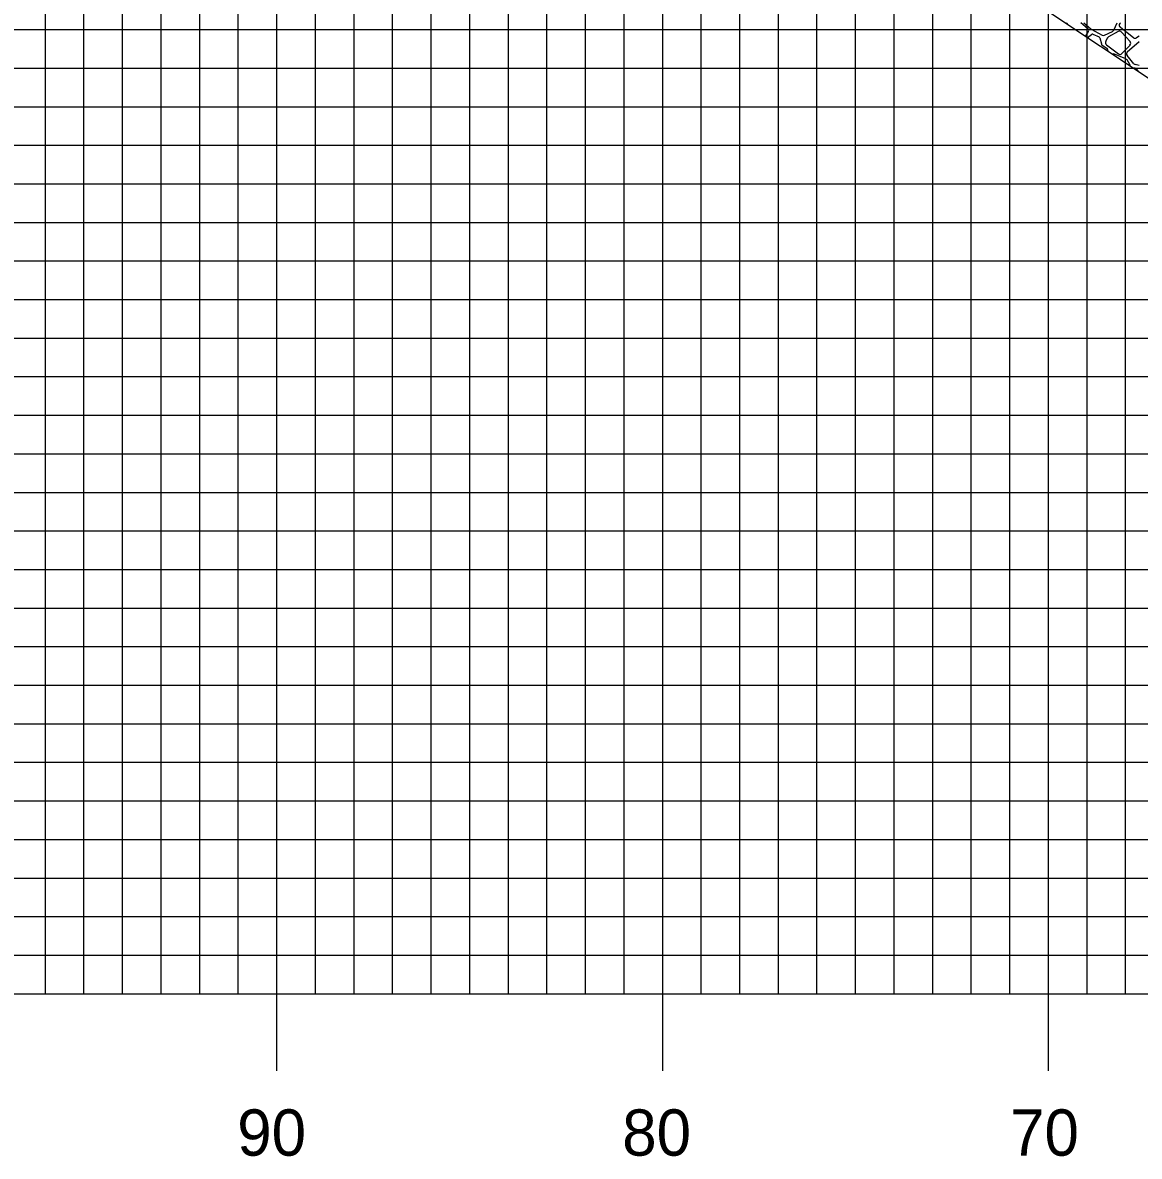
# Model space of a CAD drawing. Extents: x 1770055 to 1770398, y 442591 to 442811.
# Drawn here: x 1770123.94 to 1770152.88, y 442679.45 to 442708.84 of the extents above; entities that cross this region are included whole.
import ezdxf

# ---------------------------------------------------------------- set-up
doc = ezdxf.new("R2010")
doc.units = 0
for name, color, linetype in [('ANNOTATION', 7, 'Continuous'), ('GRUBBING IN FILL', 7, 'Continuous'), ('H_V ANNOTATION', 7, 'Continuous'), ('MAJOR', 7, 'Continuous'), ('MINOR', 7, 'Continuous')]:
    doc.layers.add(name, color=color, linetype=linetype)

msp = doc.modelspace()

# ---------------------------------------------------------------- linework, layer by layer
at = {"layer": 'ANNOTATION'}
msp.add_lwpolyline([(1770184.461, 442686.509), (1770130.169, 442722.703), (1770129.162, 442723.293), (1770128.291, 442723.662), (1770127.48, 442723.874), (1770126.762, 442723.946)], dxfattribs=at)
at = {"layer": 'GRUBBING IN FILL'}
for p, q in [((1770151.015, 442708.844), (1770150.997, 442708.817)), ((1770151.548, 442708.687), (1770151.367, 442708.844)), ((1770151.444, 442708.844), (1770151.625, 442708.682)), ((1770152.221, 442708.652), (1770152.304, 442708.844)), ((1770152.374, 442708.821), (1770152.392, 442708.844)), ((1770151.496, 442708.503), (1770151.559, 442708.597)), ((1770151.536, 442708.459), (1770151.645, 442708.541)), ((1770151.638, 442708.673), (1770151.917, 442708.52)), ((1770151.679, 442708.544), (1770151.842, 442708.473)), ((1770151.979, 442708.518), (1770152.188, 442708.618)), ((1770152.337, 442708.616), (1770152.083, 442708.476)), ((1770152.445, 442708.677), (1770152.385, 442708.725)), ((1770152.642, 442708.354), (1770152.421, 442708.601)), ((1770152.565, 442708.58), (1770152.446, 442708.677)), ((1770152.733, 442708.455), (1770152.567, 442708.578)), ((1770151.861, 442708.449), (1770151.899, 442708.293)), ((1770151.912, 442708.273), (1770152.047, 442708.174)), ((1770152.055, 442708.447), (1770152.01, 442708.358)), ((1770152.03, 442708.273), (1770152.341, 442708.035)), ((1770152.432, 442708.042), (1770152.641, 442708.262)), ((1770152.571, 442708.087), (1770152.882, 442708.36)), ((1770152.882, 442708.495), (1770152.809, 442708.451)), ((1770152.061, 442708.152), (1770152.068, 442708.103)), ((1770152.533, 442707.903), (1770152.24, 442708.028)), ((1770152.741, 442707.78), (1770152.564, 442707.992)), ((1770152.638, 442707.762), (1770152.564, 442707.877)), ((1770152.882, 442707.73), (1770152.776, 442707.758)), ((1770152.807, 442707.642), (1770152.864, 442707.573))]:
    msp.add_line(p, q, dxfattribs=at)
for centre, major_axis, start_param, end_param in [((1770152.428, 442708.779), (0, -0.0683), 4.048343, 5.608444), ((1770151.503, 442708.635), (0, -0.0683), 0.977446, 2.424153), ((1770151.67, 442708.733), (0, -0.0683), 5.554357, 5.782172), ((1770151.665, 442708.513), (0, 0.0342), 5.866747, 6.924845), ((1770152.159, 442708.68), (0, -0.0683), 0.443382, 1.163165), ((1770152.37, 442708.556), (0, 0.0683), 5.44252, 6.785098), ((1770152.403, 442708.624), (0, 0.0683), 5.600869, 5.608444), ((1770152.608, 442708.633), (0, -0.0683), 5.600869, 5.645637), ((1770151.44, 442708.541), (0, -0.0683), 0.754677, 0.977446), ((1770151.828, 442708.441), (0, 0.0342), 4.95256, 5.866747), ((1770151.933, 442708.301), (0, -0.0342), 4.95256, 5.649393), ((1770151.95, 442708.58), (0, -0.0683), 5.782172, 6.726567), ((1770152.072, 442708.327), (0, 0.0683), 1.108164, 2.48948), ((1770152.116, 442708.416), (0, 0.0683), 0.501913, 1.108164), ((1770152.591, 442708.309), (0, -0.0683), 0.810393, 2.300927), ((1770152.774, 442708.51), (0, -0.0683), 5.645637, 6.81814), ((1770152.027, 442708.146), (0, 0.0342), 4.865038, 5.649393), ((1770152.213, 442707.965), (0, 0.0683), 5.881372, 6.72794), ((1770152.383, 442708.089), (0, -0.0683), 5.631073, 7.093578), ((1770152.616, 442708.036), (0, -0.0683), 3.861663, 5.40978), ((1770152.507, 442707.84), (0, 0.0683), 5.287694, 5.881372), ((1770152.581, 442707.725), (0, -0.0683), 1.447128, 2.146101), ((1770152.755, 442707.598), (0, 0.0683), 5.401291, 6.647513), ((1770152.793, 442707.824), (0, -0.0683), 5.40978, 6.025862)]:
    msp.add_ellipse(centre, major_axis=major_axis, ratio=0.99895, start_param=start_param, end_param=end_param, dxfattribs=at)
at = {"layer": 'MAJOR'}
for p, q in [((1770130.528, 442683.665), (1770130.528, 442733.665)), ((1770140.528, 442683.665), (1770140.528, 442733.665)), ((1770150.528, 442683.665), (1770150.528, 442733.665)), ((1770080.528, 442708.665), (1770360.528, 442708.665)), ((1770080.528, 442703.665), (1770360.528, 442703.665)), ((1770080.528, 442698.665), (1770360.528, 442698.665)), ((1770080.528, 442693.665), (1770360.528, 442693.665)), ((1770080.528, 442688.665), (1770360.528, 442688.665)), ((1770080.528, 442683.665), (1770360.528, 442683.665)), ((1770080.528, 442683.665), (1770360.528, 442683.665)), ((1770130.528, 442681.661), (1770130.528, 442683.665)), ((1770140.528, 442681.661), (1770140.528, 442683.665)), ((1770150.528, 442681.661), (1770150.528, 442683.665))]:
    msp.add_line(p, q, dxfattribs=at)
at = {"layer": 'MINOR'}
for p, q in [((1770124.528, 442683.665), (1770124.528, 442733.665)), ((1770125.528, 442683.665), (1770125.528, 442733.665)), ((1770126.528, 442683.665), (1770126.528, 442733.665)), ((1770127.528, 442683.665), (1770127.528, 442733.665)), ((1770128.528, 442683.665), (1770128.528, 442733.665)), ((1770129.528, 442683.665), (1770129.528, 442733.665)), ((1770131.528, 442683.665), (1770131.528, 442733.665)), ((1770132.528, 442683.665), (1770132.528, 442733.665)), ((1770133.528, 442683.665), (1770133.528, 442733.665)), ((1770134.528, 442683.665), (1770134.528, 442733.665)), ((1770135.528, 442683.665), (1770135.528, 442733.665)), ((1770136.528, 442683.665), (1770136.528, 442733.665)), ((1770137.528, 442683.665), (1770137.528, 442733.665)), ((1770138.528, 442683.665), (1770138.528, 442733.665)), ((1770139.528, 442683.665), (1770139.528, 442733.665)), ((1770141.528, 442683.665), (1770141.528, 442733.665)), ((1770142.528, 442683.665), (1770142.528, 442733.665)), ((1770143.528, 442683.665), (1770143.528, 442733.665)), ((1770144.528, 442683.665), (1770144.528, 442733.665)), ((1770145.528, 442683.665), (1770145.528, 442733.665)), ((1770146.528, 442683.665), (1770146.528, 442733.665)), ((1770147.528, 442683.665), (1770147.528, 442733.665)), ((1770148.528, 442683.665), (1770148.528, 442733.665)), ((1770149.528, 442683.665), (1770149.528, 442733.665)), ((1770151.528, 442683.665), (1770151.528, 442733.665)), ((1770152.528, 442683.665), (1770152.528, 442733.665)), ((1770080.528, 442707.665), (1770360.528, 442707.665)), ((1770080.528, 442706.665), (1770360.528, 442706.665)), ((1770080.528, 442705.665), (1770360.528, 442705.665)), ((1770080.528, 442704.665), (1770360.528, 442704.665)), ((1770080.528, 442702.665), (1770360.528, 442702.665)), ((1770080.528, 442701.665), (1770360.528, 442701.665)), ((1770080.528, 442700.665), (1770360.528, 442700.665)), ((1770080.528, 442699.665), (1770360.528, 442699.665)), ((1770080.528, 442697.665), (1770360.528, 442697.665)), ((1770080.528, 442696.665), (1770360.528, 442696.665)), ((1770080.528, 442695.665), (1770360.528, 442695.665)), ((1770080.528, 442694.665), (1770360.528, 442694.665)), ((1770080.528, 442692.665), (1770360.528, 442692.665)), ((1770080.528, 442691.665), (1770360.528, 442691.665)), ((1770080.528, 442690.665), (1770360.528, 442690.665)), ((1770080.528, 442689.665), (1770360.528, 442689.665)), ((1770080.528, 442687.665), (1770360.528, 442687.665)), ((1770080.528, 442686.665), (1770360.528, 442686.665)), ((1770080.528, 442685.665), (1770360.528, 442685.665)), ((1770080.528, 442684.665), (1770360.528, 442684.665))]:
    msp.add_line(p, q, dxfattribs=at)

# ---------------------------------------------------------------- texts
at = {"layer": 'H_V ANNOTATION'}
for s, p in [('90', (1770129.5, 442679.465)), ('80', (1770139.479, 442679.465)), ('70', (1770149.532, 442679.465))]:
    msp.add_text(s, height=1.2, dxfattribs=at).set_placement(p)

doc.saveas('drawing.dxf')
